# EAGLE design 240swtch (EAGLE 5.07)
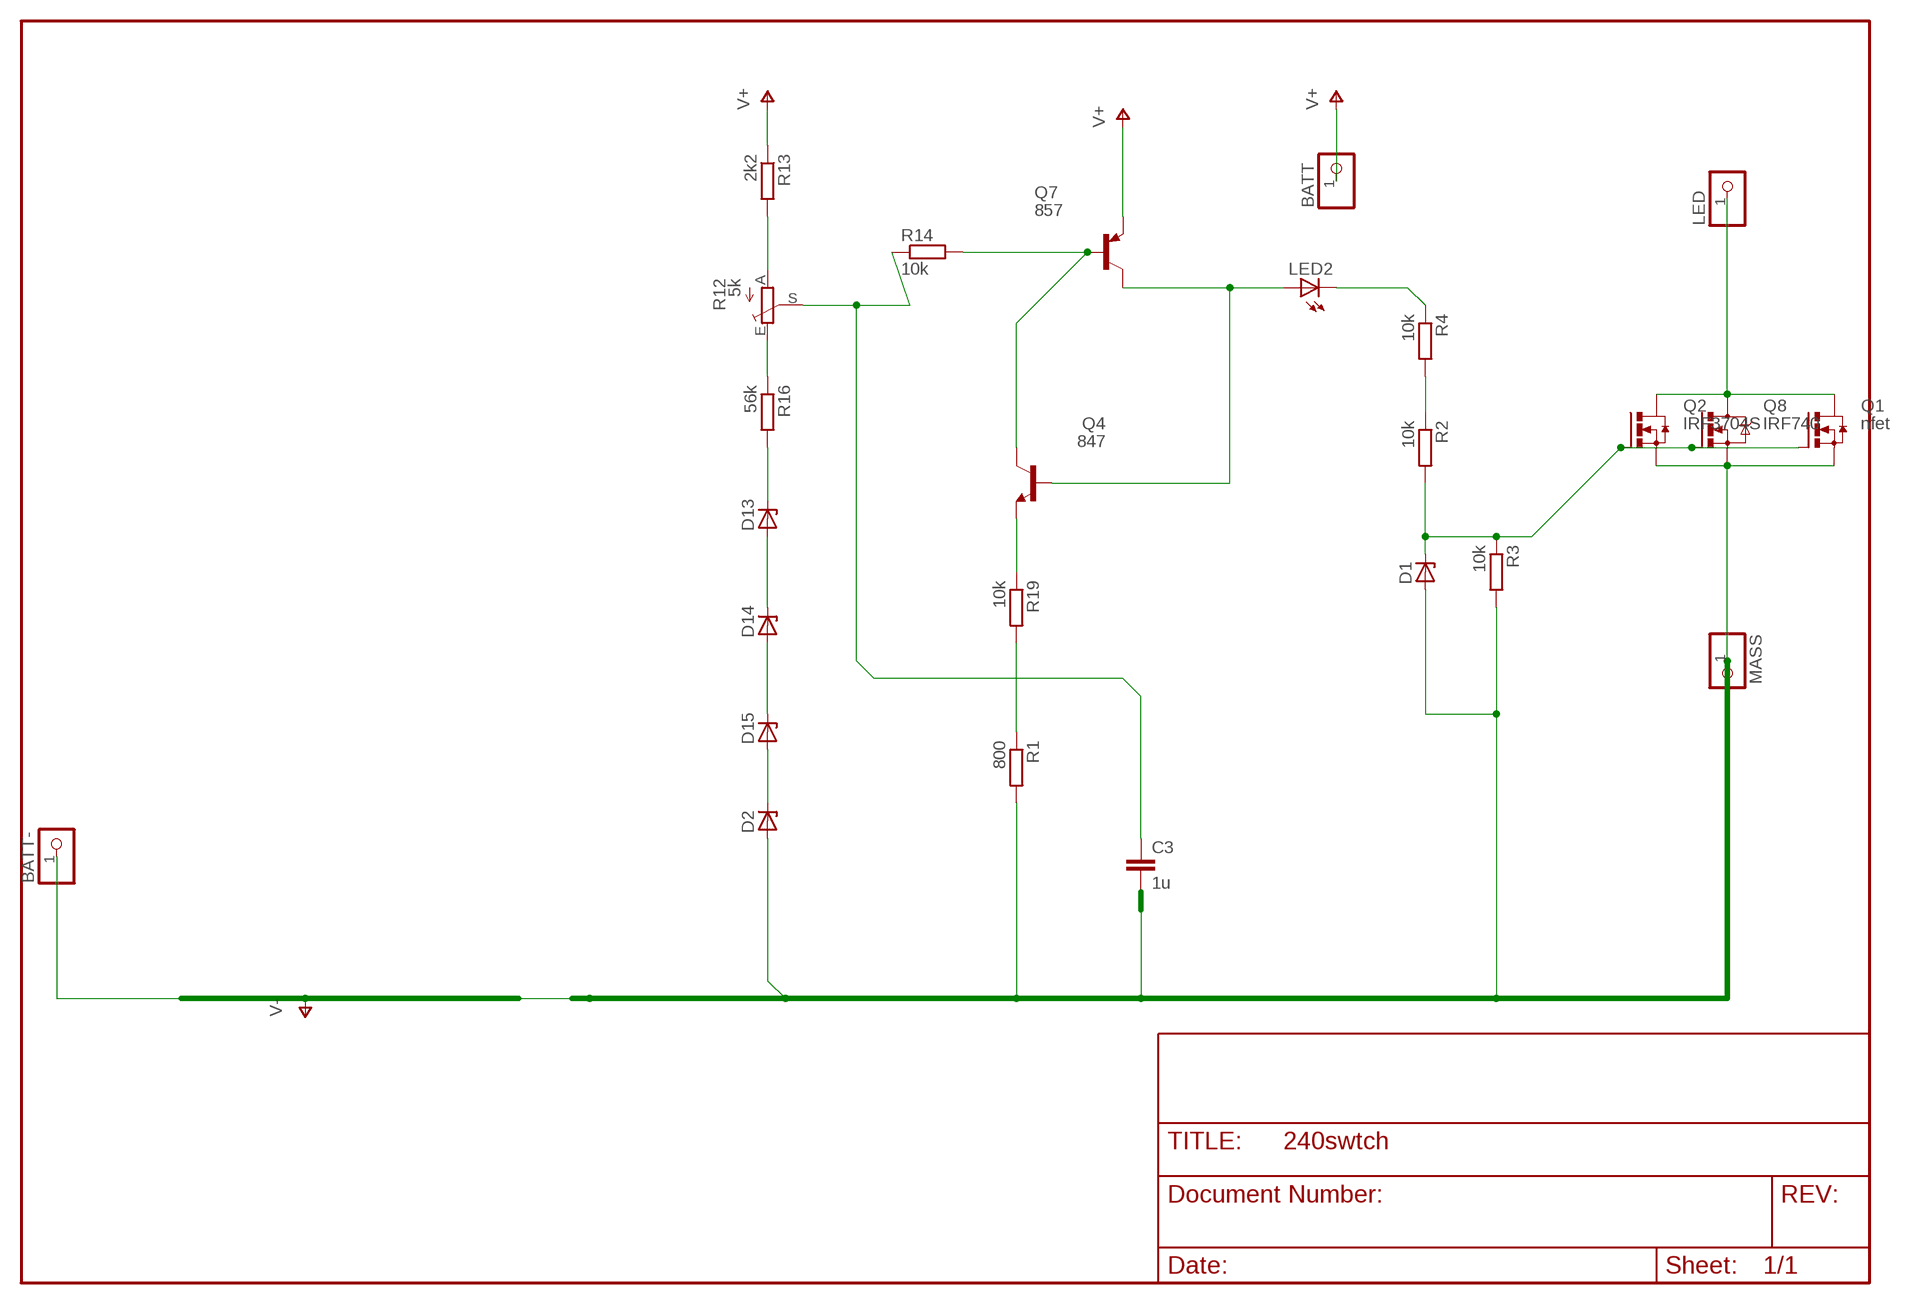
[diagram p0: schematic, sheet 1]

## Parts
BATT  PINHD-1X1  [1X01]
BATT-  PINHD-1X1  [1X01]
C3  1u  C-EUC1206  [C1206]
D1  ZENER-DIODESOD80C  [SOD80C]
D2  ZENER-DIODESOD80C  [SOD80C]
D13  ZENER-DIODESOD80C  [SOD80C]
D14  ZENER-DIODESOD80C  [SOD80C]
D15  ZENER-DIODESOD80C  [SOD80C]
LED  PINHD-1X1  [1X01]
LED2  LEDSMT1206  [1206]
MASS  PINHD-1X1  [1X01]
Q1  nfet  N-HEXFET_DPAK-  [TO252]
Q2  IRF3704S  [D2PACK]
Q4  847  BC847ALT1SMD  [SOT23]
Q7  857  BC857ALT1SMD  [SOT23-BEC]
Q8  IRF740  [TO220BV]
R1  800  R-EU_R1206  [R1206]
R2  10k  R-EU_R1206  [R1206]
R3  10k  R-EU_R1206  [R1206]
R4  10k  R-EU_R1206  [R1206]
R12  5k  TRIM_EU-S64W  [S64W]
R13  2k2  R-EU_R0805  [R0805]
R14  10k  R-EU_R0805  [R0805]
R16  56k  R-EU_R1206  [R1206]
R19  10k  R-EU_R1206  [R1206]

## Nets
N$1: D1.C Q1.1(G) Q2.1(G) Q8.G R2.2 R3.1
N$2: LED2.C R4.1
N$4: D13.C R16.2
N$5: LED2.A Q4.1(B) Q7.C
N$6: R2.1 R4.2
N$7: Q4.3(C) Q7.B R14.2
N$9: R1.1 R19.2
N$11: Q4.2(E) R19.1
N$12: R12.E R16.1
N$13: D2.C D15.A
N$23: D14.A D15.C
N$24: D13.A D14.C
N$26: R12.A R13.2
N$27: C3.1 R12.S R14.1
V+: BATT.1 Q7.E R13.1
V-: BATT-.1 C3.2 D1.A D2.A MASS.1 Q1.2(S) Q2.3(S) Q8.S R1.2 R3.2
VOUT: LED.1 Q1.3(D) Q2.2(D) Q8.D

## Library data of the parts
BATT BATT- LED MASS = pinhead:PINHD-1X1: PIN HEADER
C3 = rcl:C-EU: CAPACITOR, European symbol
D1 D2 D13-D15 = diode:ZENER-DIODE: Z-Diode
LED2 = led:LED: LED
Q1 = transistor-power:N-HEXFET_?-*: HEXFET® Power MOSFET
Q2 = transistor-power:IRF3704: SMPS MOSFET HEXFET® Power MOSFET Source: http://www.irf.com/product-info/datasheets/data/irf3704.pdf
Q4 = transistor-npn:BC847*: NPN Transistor
Q7 = transistor-pnp:BC857*: PNP Transistror
Q8 = transistor-power:IRF740: N-CHANNEL MOS FET
R1-R4 R13 R14 R16 R19 = rcl:R-EU_: RESISTOR, European symbol
R12 = pot:TRIM_EU-: POTENTIOMETER

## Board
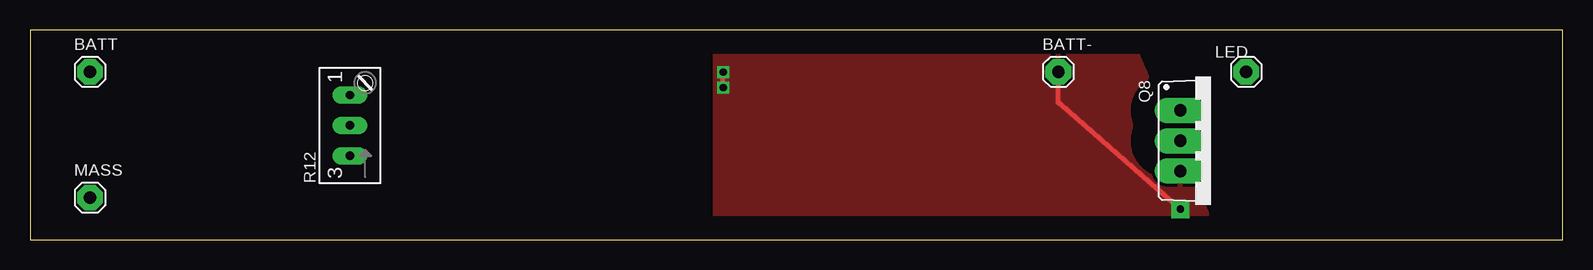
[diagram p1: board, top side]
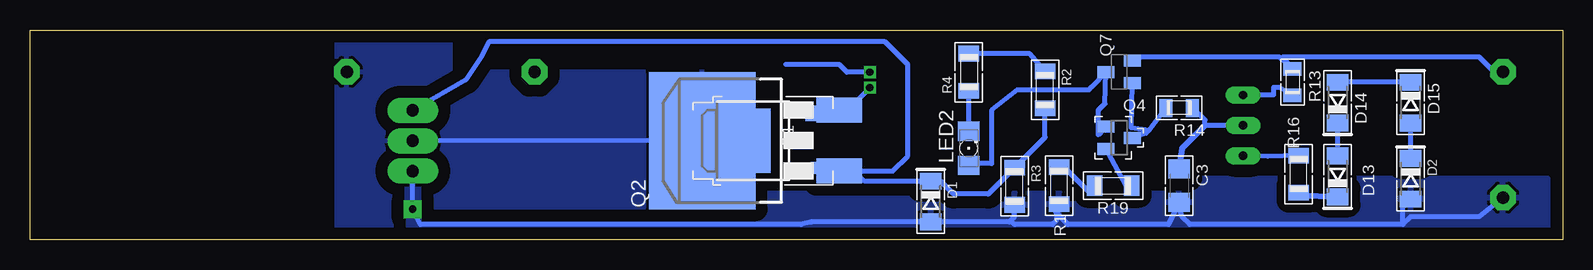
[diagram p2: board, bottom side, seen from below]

Size 127.79 x 17.5 mm. Coordinates in mm from the lower left corner, seen from the top.
Outline: 0,0 127.79,0 127.79,17.5 0,17.5 0,0
Copper layers (1*16): Top 0.035mm / dielectric 1.5mm / Bottom 0.035mm
Design rules "default *": minimum track width 10mil, minimum drill 24mil, track to track 8mil, track to pad 8mil, pad to pad 8mil, via to via 8mil, smd to smd 8mil, copper to edge 30mil, drill to drill 8mil, minimum pad ring 15mil, minimum via ring 8mil, stop-mask expansion 4mil, vias tented up to drill 0mil, thermal gap 10mil

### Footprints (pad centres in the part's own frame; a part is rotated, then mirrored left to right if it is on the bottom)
1X01 = drill 1.016 octagon: 1 0,0
C1206 = smd 1.6 x 1.8: 1 -1.4,0; 2 1.4,0
SOD80C = smd 1.4 x 1.8: A 1.7,0; C -1.7,0
1206 = smd 1.6 x 1.803: A -1.422,0; C 1.422,0
TO252 = smd 1 x 1.6: 1 -2.28,-3.53 | smd 1.27 x 2.54: 2 2.28,-3.53 | smd 5.4 x 6.2: 3 0,3.77
D2PACK = smd 2.083 x 3.81: 1 -2.54,-8.89; 3 2.54,-8.89 | smd 11.43 x 8.89: 2 0,2.54
SOT23 = smd 1 x 1.4: 1 -0.95,-1.1; 2 0.95,-1.1; 3 0,1.1
SOT23-BEC = smd 1 x 1.4: B -0.95,-1.1; C 0,1.1; E 0.95,-1.1
TO220BV = drill 1.016 long: D 0,-2.54; G -2.54,-2.54; S 2.54,-2.54
R1206 = smd 1.3 x 1.7: 1 -1.55,0; 2 1.55,0
S64W = drill 0.7 long: A 2.54,1.27; E -2.54,1.27; S 0,1.27
R0805 = smd 1.1 x 1.5: 1 -1.1,0; 2 1.1,0

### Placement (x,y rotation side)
BATT  5,14 0 top
BATT-  85.72,14 0 top
C3  32,4.5 270 bottom
D1  52.7,3.17 270 bottom
D2  12.7,5.08 270 bottom
D13  18.79,5.27 90 bottom
D14  18.79,11.43 90 bottom
D15  12.7,11.43 270 bottom
LED  101.38,14 0 top
LED2  49.53,7.62 90 bottom
MASS  5,3.5 0 top
Q1  65.41,8.26 90 bottom
Q2  69.22,8.26 90 bottom
Q4  37,8.5 270 bottom
Q7  37,14 90 bottom
Q8  98.42,8.25 270 top
R1  42,4.5 270 bottom
R2  43.18,12.5 270 bottom
R3  45.72,4.45 270 bottom
R4  49.53,13.97 90 bottom
R12  27.94,9.53 90 top
R13  22.54,13.14 270 bottom
R14  32,11 180 bottom
R16  22.03,5.46 270 bottom
R19  37.5,4.5 180 bottom

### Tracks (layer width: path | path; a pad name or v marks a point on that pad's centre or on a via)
N$1
  Bottom 0.406: R2.2 43.18,8.54 R3.1 47.91,3.81 50.8,3.81 51.87,4.88 D1.C 58.22,4.88 59.05,5.71 Q2.1 | Q2.1 55.88,5.71 54.61,6.99 54.61,14.61 56.52,16.51 89.53,16.51 90.17,15.24 91.44,13.34 Q8.G | Q2.1 61.62,5.71 Q1.1
N$2
  Bottom 0.406: LED2.C R4.1
N$4
  Bottom 0.5: D13.C 22.02,3.63 R16.2
N$5
  Bottom 0.406: LED2.A 49.38,6.35 47.62,6.35 47.62,10.79 45.5,12.5 39.5,12.5 39.37,12.7 Q7.C 38.18,11.35 38.73,10.79 38.73,8.74 Q4.1
N$6
  Bottom 0.406: R4.2 44.45,15.52 R2.1
N$7
  Bottom 0.406: Q4.3 34.76,8.89 34.52,9.12 | 34.52,9.12 R14.2 | Q7.B 35.98,9.31 34.52,9.12
N$9
  Bottom 0.406: R19.2 39.52,3.96 41.27,5.71 42.22,5.71 R1.1
N$11
  Bottom 0.406: R19.1 36.42,4.53 Q4.2
N$12
  Bottom 0.406: R12.E 24.64,6.95 R16.1
N$13
  Bottom 0.406: D2.C D15.A
N$23
  Bottom 0.406: D15.C D14.A
N$24
  Bottom 0.406: D13.A D14.C
N$26
  Bottom 0.406: R12.A 24.13,12.06 24.13,12.7 23.66,12.7 R13.2
N$27
  Bottom 0.406: R12.S 29.84,9.53 29.84,9.99 R14.1
  Bottom 0.5: C3.1 31.75,7.62 29.84,9.53
V+
  Bottom 0.406: Q7.E 35.98,14.82 35.56,15.24 23.66,15.24 R13.1 23.32,15.24 6.99,15.24 5.75,14 BATT.1
V-  (via drill 0.6, 0.6 pad 1.5)
  Top 0.406: BATT-.1 85.72,11.43 v95.89,2.54 | v57.78,12.7 v57.78,13.97
  Bottom 0.406: 13.34,1.27 31.11,1.27 31.75,1.91 C3.2 32.89,1.27 41.27,1.27 42.28,2.28 R1.2 42.28,1.53 42.55,1.27 45.72,1.27 46.04,1.59 | 13.34,1.27 13.34,2.75 D2.A | MASS.1 6.99,1.91 12.7,1.91 13.34,1.27 | Q8.S v95.89,2.54 95.25,1.27 63.5,1.27 62.66,1.48 D1.A 46.15,1.48 46.04,1.59 | 64.77,14.61 60.33,14.61 59.69,13.97 v57.78,13.97 | 46.04,1.59 45.72,1.91 R3.2 | Q1.2 60.59,10.54 Q2.3 59.69,10.79 v57.78,12.7
  pour Top (isolate 2): 57.15,15.88 92.08,15.88 98.42,1.27 57.15,1.27
  pour Bottom (isolate 1, rank 2): 1.27,5.08 31.75,5.08 33.02,3.81 93.34,3.81 95.25,5.71 97.79,5.71 97.79,1.27 97.16,0.64 1.27,0.64
VOUT
  Bottom 0.406: Q8.D Q2.2 70.48,8.26 69.85,7.62 69.81,7.62 Q1.3
  pour Bottom (isolate 1): 67.31,13.97 92.71,13.97 92.71,16.51 102.23,16.51 102.23,0 93.34,1.27 67.94,1.27 67.31,2.54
